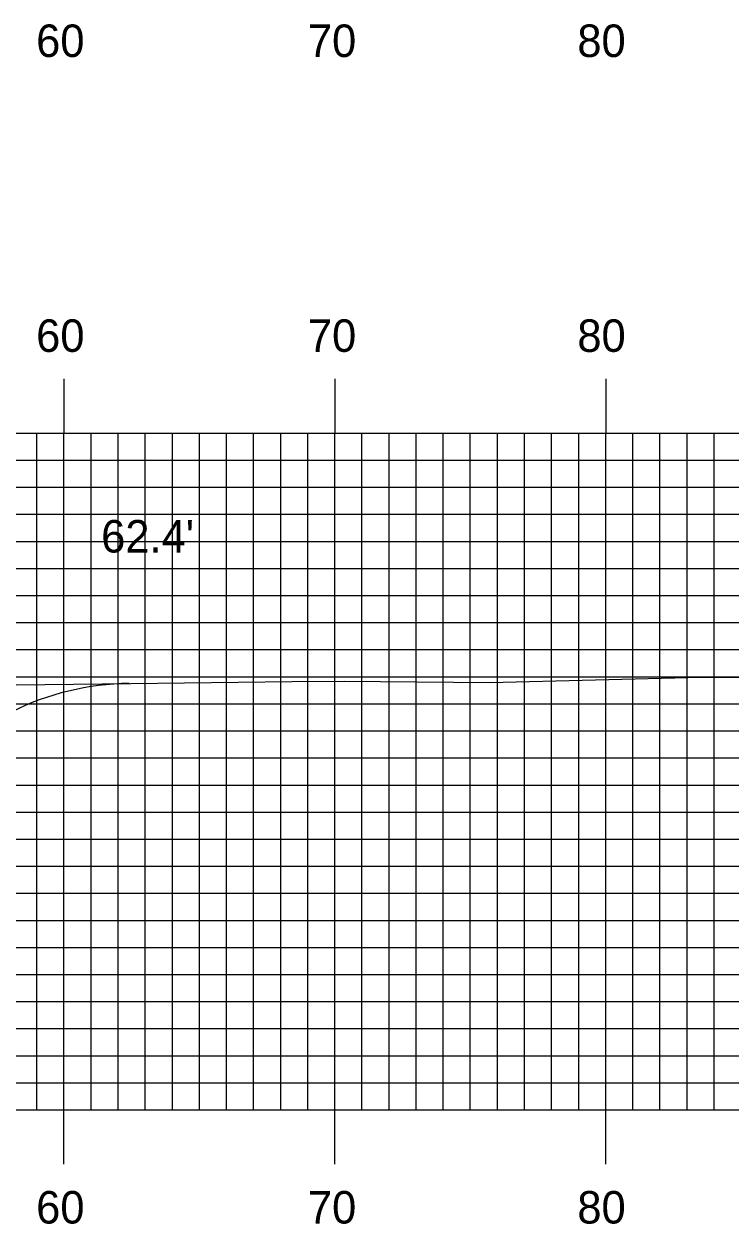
# Model space of a CAD drawing. Extents: x 852087 to 852430, y 366898 to 367118.
# Drawn here: x 852311.06 to 852337.15, y 366960.85 to 367005.18 of the extents above; entities that cross this region are included whole.
import ezdxf

# ---------------------------------------------------------------- set-up
doc = ezdxf.new("R2010")
doc.units = 0
for name, color, linetype in [('D_Roadway_Centerline', 7, 'Continuous'), ('D_Text_Standard', 7, 'Continuous'), ('H_V ANNOTATION', 7, 'Continuous'), ('MAJOR', 7, 'Continuous'), ('MINOR', 7, 'Continuous'), ('S_Roadway_Centerline', 7, 'Continuous')]:
    doc.layers.add(name, color=color, linetype=linetype)

msp = doc.modelspace()

# ---------------------------------------------------------------- linework, layer by layer
at = {"layer": 'D_Roadway_Centerline'}
msp.add_arc((852315.052, 366970.819), 10, 90.645, 116.5651, dxfattribs=at)
at = {"layer": 'MAJOR'}
for p, q in [((852312.531, 366992.071), (852312.531, 366990.067)), ((852322.531, 366992.071), (852322.531, 366990.067)), ((852332.531, 366992.071), (852332.531, 366990.067)), ((852112.531, 366990.067), (852392.531, 366990.067)), ((852112.531, 366990.067), (852392.531, 366990.067)), ((852312.531, 366965.067), (852312.531, 366990.067)), ((852322.531, 366965.067), (852322.531, 366990.067)), ((852332.531, 366965.067), (852332.531, 366990.067)), ((852112.531, 366985.067), (852392.531, 366985.067)), ((852112.531, 366980.067), (852392.531, 366980.067)), ((852112.531, 366975.067), (852392.531, 366975.067)), ((852112.531, 366970.067), (852392.531, 366970.067)), ((852112.531, 366965.067), (852392.531, 366965.067)), ((852112.531, 366965.067), (852392.531, 366965.067)), ((852312.531, 366963.063), (852312.531, 366965.067)), ((852322.531, 366963.063), (852322.531, 366965.067)), ((852332.531, 366963.063), (852332.531, 366965.067))]:
    msp.add_line(p, q, dxfattribs=at)
at = {"layer": 'MINOR'}
for p, q in [((852311.531, 366965.067), (852311.531, 366990.067)), ((852313.531, 366965.067), (852313.531, 366990.067)), ((852314.531, 366965.067), (852314.531, 366990.067)), ((852315.531, 366965.067), (852315.531, 366990.067)), ((852316.531, 366965.067), (852316.531, 366990.067)), ((852317.531, 366965.067), (852317.531, 366990.067)), ((852318.531, 366965.067), (852318.531, 366990.067)), ((852319.531, 366965.067), (852319.531, 366990.067)), ((852320.531, 366965.067), (852320.531, 366990.067)), ((852321.531, 366965.067), (852321.531, 366990.067)), ((852323.531, 366965.067), (852323.531, 366990.067)), ((852324.531, 366965.067), (852324.531, 366990.067)), ((852325.531, 366965.067), (852325.531, 366990.067)), ((852326.531, 366965.067), (852326.531, 366990.067)), ((852327.531, 366965.067), (852327.531, 366990.067)), ((852328.531, 366965.067), (852328.531, 366990.067)), ((852329.531, 366965.067), (852329.531, 366990.067)), ((852330.531, 366965.067), (852330.531, 366990.067)), ((852331.531, 366965.067), (852331.531, 366990.067)), ((852333.531, 366965.067), (852333.531, 366990.067)), ((852334.531, 366965.067), (852334.531, 366990.067)), ((852335.531, 366965.067), (852335.531, 366990.067)), ((852336.531, 366965.067), (852336.531, 366990.067)), ((852112.531, 366989.067), (852392.531, 366989.067)), ((852112.531, 366988.067), (852392.531, 366988.067)), ((852112.531, 366987.067), (852392.531, 366987.067)), ((852112.531, 366986.067), (852392.531, 366986.067)), ((852112.531, 366984.067), (852392.531, 366984.067)), ((852112.531, 366983.067), (852392.531, 366983.067)), ((852112.531, 366982.067), (852392.531, 366982.067)), ((852112.531, 366981.067), (852392.531, 366981.067)), ((852112.531, 366979.067), (852392.531, 366979.067)), ((852112.531, 366978.067), (852392.531, 366978.067)), ((852112.531, 366977.067), (852392.531, 366977.067)), ((852112.531, 366976.067), (852392.531, 366976.067)), ((852112.531, 366974.067), (852392.531, 366974.067)), ((852112.531, 366973.067), (852392.531, 366973.067)), ((852112.531, 366972.067), (852392.531, 366972.067)), ((852112.531, 366971.067), (852392.531, 366971.067)), ((852112.531, 366969.067), (852392.531, 366969.067)), ((852112.531, 366968.067), (852392.531, 366968.067)), ((852112.531, 366967.067), (852392.531, 366967.067)), ((852112.531, 366966.067), (852392.531, 366966.067))]:
    msp.add_line(p, q, dxfattribs=at)
at = {"layer": 'S_Roadway_Centerline'}
msp.add_lwpolyline([(852266.889, 366980.55), (852273.177, 366980.595), (852287.611, 366980.884), (852298.913, 366980.87), (852305.044, 366980.708), (852307.583, 366980.736), (852315.003, 366980.819), (852320.944, 366980.889), (852322.873, 366980.908), (852328.245, 366980.851), (852336.05, 366981.045), (852337.951, 366981.036)], dxfattribs=at)

# ---------------------------------------------------------------- texts
at = {"layer": 'D_Text_Standard'}
msp.add_text("62.4'", height=1.2, dxfattribs=at).set_placement((852313.903, 366985.655))
at = {"layer": 'H_V ANNOTATION'}
for s, p in [('60', (852311.503, 367003.961)), ('70', (852321.535, 367003.961)), ('80', (852331.482, 367003.961)), ('60', (852311.503, 366993.067)), ('70', (852321.535, 366993.067)), ('80', (852331.482, 366993.067)), ('60', (852311.503, 366960.867)), ('70', (852321.535, 366960.867)), ('80', (852331.482, 366960.867))]:
    msp.add_text(s, height=1.2, dxfattribs=at).set_placement(p)

doc.saveas('drawing.dxf')
